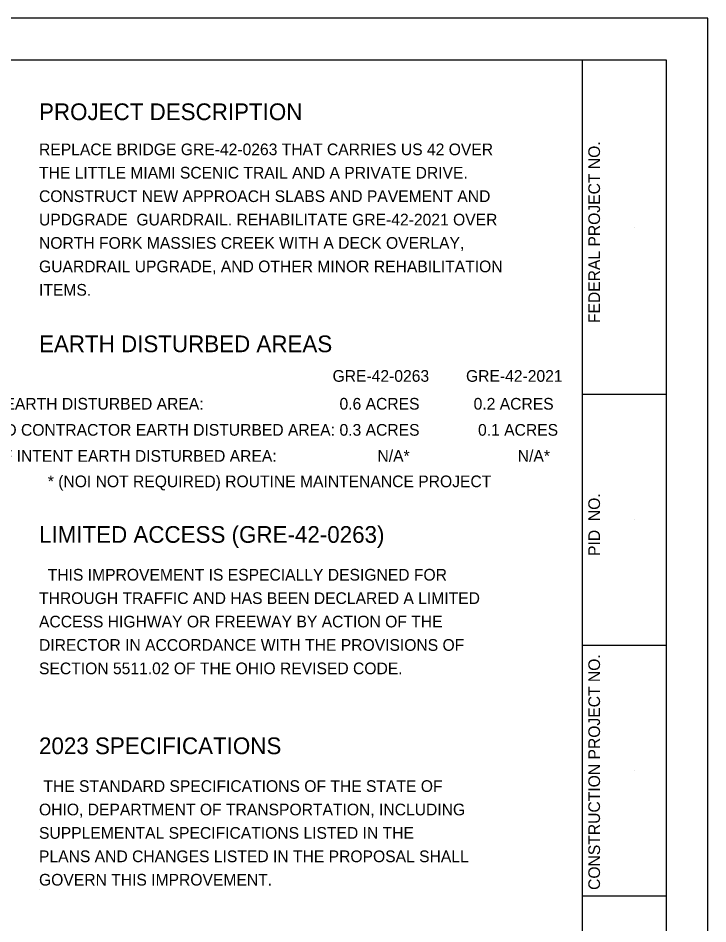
# Model space of a CAD drawing. Extents: x -19.5 to 44.1, y 0 to 22.
# Drawn here: x 25.75 to 34, y 11.17 to 22 of the extents above; entities that cross this region are included whole.
import ezdxf

# ---------------------------------------------------------------- set-up
doc = ezdxf.new("R2010")
doc.units = 0
for name, color, linetype in [('SH_Border', 7, 'Continuous'), ('SH_Cut_Line', 7, 'Continuous'), ('SH_Data', 7, 'Continuous'), ('SH_Text', 7, 'Continuous')]:
    doc.layers.add(name, color=color, linetype=linetype)

msp = doc.modelspace()

# ---------------------------------------------------------------- linework, layer by layer
at = {"layer": 'SH_Border'}
for p, q in [((32.5, 0.5), (32.5, 21.5)), ((32.5, 17.5), (33.5, 17.5)), ((32.5, 14.5), (33.5, 14.5)), ((32.5, 11.5), (33.5, 11.5))]:
    msp.add_line(p, q, dxfattribs=at)
msp.add_lwpolyline([(2, 21.5), (33.5, 21.5), (33.5, 0.5), (2, 0.5)], close=True, dxfattribs=at)
at = {"layer": 'SH_Cut_Line'}
msp.add_lwpolyline([(0, 0), (34, 0), (34, 22), (0, 22)], close=True, dxfattribs=at)
at = {"layer": 'SH_Data'}
for p, q in [((33.125, 19.5), (33.125, 19.5)), ((33.125, 16), (33.125, 16)), ((33.125, 13), (33.125, 13)), ((26, 11.572), (26, 11.572))]:
    msp.add_line(p, q, dxfattribs=at)

# ---------------------------------------------------------------- texts
for s, height, p in [('PROJECT DESCRIPTION', 0.2, (26, 20.78)), ('EARTH DISTURBED AREAS', 0.2, (26, 18.004)), ('GRE-42-0263', 0.14, (29.511, 17.65)), ('GRE-42-2021', 0.14, (31.107, 17.65)), ('PROJECT EARTH DISTURBED AREA:', 0.14, (24.661, 17.317)), ('0.6 ACRES', 0.14, (29.594, 17.317)), ('0.2 ACRES', 0.14, (31.198, 17.317)), ('ESTIMATED CONTRACTOR EARTH DISTURBED AREA:', 0.14, (24.661, 17.005)), ('0.3 ACRES', 0.14, (29.594, 17.005)), ('0.1 ACRES', 0.14, (31.251, 17.005)), ('NOTICE OF INTENT EARTH DISTURBED AREA:', 0.14, (24.661, 16.693)), ('N/A*', 0.14, (30.048, 16.693)), ('N/A*', 0.14, (31.726, 16.693)), ('* (NOI NOT REQUIRED) ROUTINE MAINTENANCE PROJECT', 0.14, (26.105, 16.389)), ('LIMITED ACCESS (GRE-42-0263)', 0.2, (26, 15.724)), ('  THIS IMPROVEMENT IS ESPECIALLY DESIGNED FOR', 0.14, (26, 15.272)), ('THROUGH TRAFFIC AND HAS BEEN DECLARED A LIMITED', 0.14, (26, 14.992)), ('ACCESS HIGHWAY OR FREEWAY BY ACTION OF THE', 0.14, (26, 14.712)), ('DIRECTOR IN ACCORDANCE WITH THE PROVISIONS OF', 0.14, (26, 14.432)), ('SECTION 5511.02 OF THE OHIO REVISED CODE.', 0.14, (26, 14.152)), ('2023 SPECIFICATIONS', 0.2, (26, 13.196)), (' THE STANDARD SPECIFICATIONS OF THE STATE OF', 0.14, (26, 12.744)), ('OHIO, DEPARTMENT OF TRANSPORTATION, INCLUDING', 0.14, (26, 12.464)), ('SUPPLEMENTAL SPECIFICATIONS LISTED IN THE', 0.14, (26, 12.184)), ('PLANS AND CHANGES LISTED IN THE PROPOSAL SHALL', 0.14, (26, 11.904)), ('GOVERN THIS IMPROVEMENT.', 0.14, (26, 11.624))]:
    msp.add_text(s, height=height, dxfattribs=at).set_placement(p)
for s, p in [('FEDERAL PROJECT NO.', (32.71, 18.352)), ('PID  NO.', (32.71, 15.567)), ('CONSTRUCTION PROJECT NO.', (32.71, 11.572))]:
    msp.add_text(s, height=0.14, rotation=90, dxfattribs=at).set_placement(p)
at = {"layer": 'SH_Text'}
for s, p in [('REPLACE BRIDGE GRE-42-0263 THAT CARRIES US 42 OVER', (26, 20.36)), ('THE LITTLE MIAMI SCENIC TRAIL AND A PRIVATE DRIVE. ', (26, 20.081)), ('CONSTRUCT NEW APPROACH SLABS AND PAVEMENT AND', (26, 19.8)), ('UPDGRADE  GUARDRAIL. REHABILITATE GRE-42-2021 OVER ', (26, 19.52)), ('NORTH FORK MASSIES CREEK WITH A DECK OVERLAY, ', (26, 19.241)), ('GUARDRAIL UPGRADE, AND OTHER MINOR REHABILITATION ', (26, 18.96)), ('ITEMS.', (26, 18.68))]:
    msp.add_text(s, height=0.14, dxfattribs=at).set_placement(p)

doc.saveas('drawing.dxf')
